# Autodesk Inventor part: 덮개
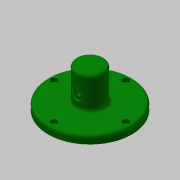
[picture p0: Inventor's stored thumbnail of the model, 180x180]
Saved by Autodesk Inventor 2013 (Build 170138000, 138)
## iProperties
Created: 2017-08
Part Number: 덮개
Material: 알루미늄 6061
Document SubType Name: Modeling
Designer: mduedu
Density: 1 g/cm^3
Author: mduedu
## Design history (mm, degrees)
sketch "스케치1"
  geometry: C1 r 52.5 at (0, 0); 1 further point
  constraints: 1 centre point, 1 coincident
  dimensions: "d55" = 105 diameter of C1
extrude "돌출1" new body sketch "스케치1" distance "d5" = 10; taper "d6" = 0 deg
sketch "스케치2"
  geometry: C1 r 17 at (0, 0); 1 further point
  constraints: 1 centre point, 1 coincident
  dimensions: "d74" = 34 diameter of C1
extrude "돌출2" join sketch "스케치2" distance "d9" = 40; taper "d10" = 0 deg
sketch "스케치3"
  geometry: C1 r 37 at (0, 0); 1 further point
  constraints: 1 centre point, 1 coincident
  dimensions: "d56" = 74 diameter of C1
extrude "돌출3" join sketch "스케치3" distance "d12" = 6; taper "d13" = 0 deg
sketch "스케치4"
  geometry: C1 r 33 at (0, 0); 1 further point
  constraints: 1 centre point, 1 coincident
  dimensions: "d57" = 66 diameter of C1
extrude "돌출4" cut sketch "스케치4" distance "d16" = 5; taper "d17" = 0 deg
sketch "스케치5"
  geometry: C1 r 9 at (0, 0); 1 further point
  constraints: 1 centre point, 1 coincident
  dimensions: "d18" = 18 diameter of C1
extrude "돌출5" cut sketch "스케치5" distance "d19" = 47; taper "d20" = 0 deg
node "작업 평면1"
sketch "스케치11"
  geometry: L1 (-52.5, -10)-(52.5, -10) reference; 2 further points
  constraints: 1 vertical alignment
  dimensions: "d78" = 26 distance from line of point (0, 16) L1
hole "구멍5" sketch "스케치11" at (0, 16) diameter "d79" = 5.917; stored, may be unused: countersink angle "d83" = 90 deg, drill point angle "d85" = 118 deg; dims "d80" = 6, "d81" = 14, "d82" = 2, "d84" = 8
fillet "모깎기9" dims "d86" = 3
fillet "모깎기5" dims "d40" = 1
sketch "스케치12"
  geometry: C1 r 2.5 at (0, 0); 1 further point
  constraints: 1 centre point, 1 coincident
  dimensions: "d87" = 5 diameter of C1
extrude "돌출6" join sketch "스케치12" distance "d88" = 3; taper "d89" = 0 deg
fillet "모깎기10" dims "d91" = 1
chamfer "모따기1" distance "d41" = 1; stored, may be unused: second distance "d42" = 2, angle "d43" = 45 deg
fillet "모깎기7" dims "d45" = 3
fillet "모깎기8" dims "d46" = 3
sketch "스케치10" dims "d59" = 90
  geometry: 3 further points
  constraints: 2 vertical alignment, 1 coincident, 2 other
hole "구멍4" sketch "스케치10" at (0, 45) diameter "d60" = 4.5; stored, may be unused: countersink angle "d64" = 90 deg, drill point angle "d66" = 118 deg; dims "d61" = 6, "d62" = 8, "d63" = 4.6, "d65" = 8
node "솔리드1"
pattern_circular "원형 패턴1" dims angle "d68" = 360 deg
